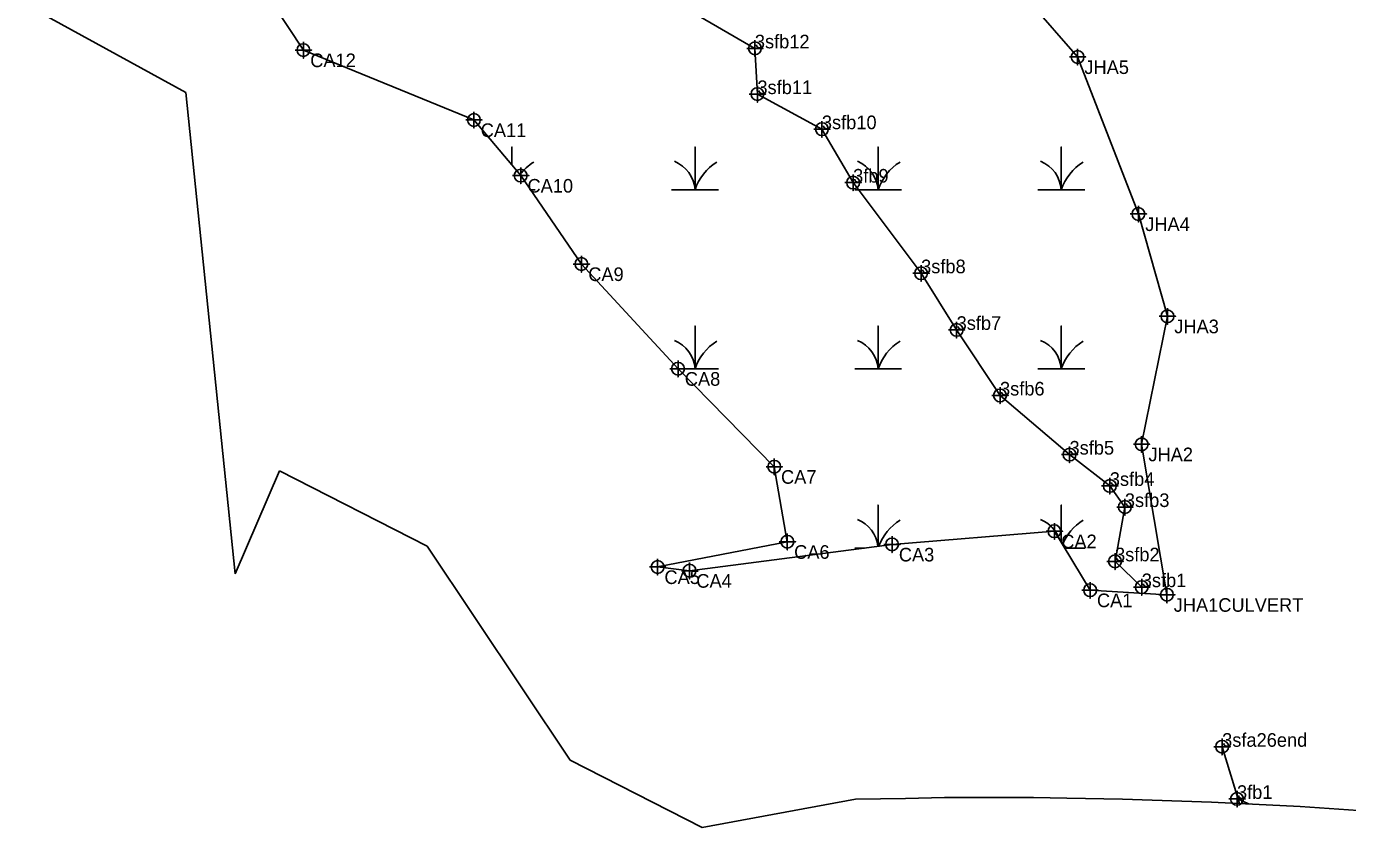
# Model space of a CAD drawing. Extents: x 2071991 to 2268989, y 436479 to 469629.
# Drawn here: x 2096416.2 to 2096901.1, y 458679.5 to 458973.7 of the extents above; entities that cross this region are included whole.
import ezdxf

# ---------------------------------------------------------------- set-up
doc = ezdxf.new("R2010")
doc.units = 0
for name, color, linetype in [('approx_PSA', 7, 'Continuous'), ('Exist Environmental Wetland Boundary', 7, 'Continuous'), ('Exist Environmental Wetland Boundary Cogo Comment', 7, 'Continuous'), ('Exist Environmental Wetland Boundary Cogo Point CELL', 7, 'Continuous'), ('Exist Hydro Jurisdictional Stream or Body of Water NEU Mitigable', 7, 'Continuous'), ('Exist Hydro Jurisdictional Stream or Body of Water NEU Mitigable Cogo Comment', 7, 'Continuous'), ('Exist Hydro Jurisdictional Stream or Body of Water NEU Mitigable Cogo Point CELL', 7, 'Continuous'), ('Exist Hydro Swamp or Marsh', 7, 'Continuous')]:
    doc.layers.add(name, color=color, linetype=linetype)

msp = doc.modelspace()

# ---------------------------------------------------------------- linework, layer by layer
at = {"layer": 'approx_PSA'}
for p, q in [((2096474.73, 458949.44), (2096416.23, 458981.59)), ((2096492.79, 458772.75), (2096474.73, 458949.44)), ((2096509.16, 458810.5), (2096492.79, 458772.75)), ((2096563.25, 458782.91), (2096509.16, 458810.5)), ((2096615.76, 458704.23), (2096563.25, 458782.91)), ((2096664.25, 458679.49), (2096615.76, 458704.23)), ((2096720.5, 458689.9), (2096664.25, 458679.49)), ((2096738.84, 458690.23), (2096720.5, 458689.9)), ((2096753.15, 458690.5), (2096738.84, 458690.23)), ((2096785.81, 458690.52), (2096753.15, 458690.5)), ((2096798.01, 458690.32), (2096785.81, 458690.52)), ((2096798.03, 458690.32), (2096798.01, 458690.32)), ((2096818.46, 458689.98), (2096798.03, 458690.32)), ((2096851.1, 458688.87), (2096818.46, 458689.98)), ((2096883.72, 458687.18), (2096851.1, 458688.87)), ((2096916.3, 458684.93), (2096883.72, 458687.18))]:
    msp.add_line(p, q, dxfattribs=at)
at = {"layer": 'Exist Environmental Wetland Boundary'}
for points in [[(2096478.67, 459024.53), (2096517.89, 458965.03), (2096580.45, 458939.37), (2096597.62, 458918.95), (2096619.91, 458886.48), (2096655.35, 458848.02), (2096690.66, 458812.02), (2096695.47, 458784.46), (2096647.88, 458775.2), (2096659.58, 458773.84), (2096733.9, 458783.48), (2096793.49, 458788.35), (2096806.6, 458766.69), (2096834.77, 458765), (2096825.49, 458820.29), (2096834.97, 458867.3), (2096824.32, 458904.85), (2096801.99, 458962.51), (2096784.25, 458982.86)], [(2096860.83, 458690.07), (2096864.73, 458688.16)]]:
    msp.add_lwpolyline(points, dxfattribs=at)
at = {"layer": 'Exist Environmental Wetland Boundary Cogo Point CELL'}
for points in [[(2096517.89, 458968.03), (2096517.89, 458962.03), (2096517.89, 458965.03), (2096520.89, 458965.03), (2096514.89, 458965.03)], [(2096801.99, 458965.51), (2096801.99, 458959.51), (2096801.99, 458962.51), (2096804.99, 458962.51), (2096798.99, 458962.51)], [(2096580.45, 458942.37), (2096580.45, 458936.37), (2096580.45, 458939.37), (2096583.45, 458939.37), (2096577.45, 458939.37)], [(2096597.62, 458921.95), (2096597.62, 458915.95), (2096597.62, 458918.95), (2096600.62, 458918.95), (2096594.62, 458918.95)], [(2096824.32, 458907.85), (2096824.32, 458901.85), (2096824.32, 458904.85), (2096827.32, 458904.85), (2096821.32, 458904.85)], [(2096619.91, 458889.48), (2096619.91, 458883.48), (2096619.91, 458886.48), (2096622.91, 458886.48), (2096616.91, 458886.48)], [(2096834.97, 458870.3), (2096834.97, 458864.3), (2096834.97, 458867.3), (2096837.97, 458867.3), (2096831.97, 458867.3)], [(2096655.35, 458851.02), (2096655.35, 458845.02), (2096655.35, 458848.02), (2096658.35, 458848.02), (2096652.35, 458848.02)], [(2096825.49, 458823.29), (2096825.49, 458817.29), (2096825.49, 458820.29), (2096828.49, 458820.29), (2096822.49, 458820.29)], [(2096690.66, 458815.02), (2096690.66, 458809.02), (2096690.66, 458812.02), (2096693.66, 458812.02), (2096687.66, 458812.02)], [(2096793.49, 458791.35), (2096793.49, 458785.35), (2096793.49, 458788.35), (2096796.49, 458788.35), (2096790.49, 458788.35)], [(2096695.47, 458787.46), (2096695.47, 458781.46), (2096695.47, 458784.46), (2096698.47, 458784.46), (2096692.47, 458784.46)], [(2096733.9, 458786.48), (2096733.9, 458780.48), (2096733.9, 458783.48), (2096736.9, 458783.48), (2096730.9, 458783.48)], [(2096647.88, 458778.2), (2096647.88, 458772.2), (2096647.88, 458775.2), (2096650.88, 458775.2), (2096644.88, 458775.2)], [(2096659.58, 458776.84), (2096659.58, 458770.84), (2096659.58, 458773.84), (2096662.58, 458773.84), (2096656.58, 458773.84)], [(2096806.6, 458769.69), (2096806.6, 458763.69), (2096806.6, 458766.69), (2096809.6, 458766.69), (2096803.6, 458766.69)], [(2096834.77, 458768), (2096834.77, 458762), (2096834.77, 458765), (2096837.77, 458765), (2096831.77, 458765)], [(2096860.49, 458693.02), (2096860.49, 458687.02), (2096860.49, 458690.02), (2096863.49, 458690.02), (2096857.49, 458690.02)]]:
    msp.add_lwpolyline(points, dxfattribs=at)
for centre in [(2096517.89, 458965.03), (2096801.99, 458962.51), (2096580.45, 458939.37), (2096597.62, 458918.95), (2096824.32, 458904.85), (2096619.91, 458886.48), (2096834.97, 458867.3), (2096655.35, 458848.02), (2096825.49, 458820.29), (2096690.66, 458812.02), (2096695.47, 458784.46), (2096793.49, 458788.35), (2096733.9, 458783.48), (2096647.88, 458775.2), (2096659.58, 458773.84), (2096806.6, 458766.69), (2096834.77, 458765), (2096860.49, 458690.02)]:
    msp.add_circle(centre, 2.34, dxfattribs=at)
at = {"layer": 'Exist Hydro Jurisdictional Stream or Body of Water NEU Mitigable'}
for points in [[(2096437.83, 459257.03), (2096456.19, 459240.49), (2096480.46, 459204.95), (2096502.68, 459180.01), (2096532.04, 459137.34), (2096548.57, 459119.82), (2096564.69, 459110.17), (2096580.46, 459082.27), (2096602.73, 459051.57), (2096614.09, 459035.56), (2096631.32, 459020.05), (2096657.61, 458980.69), (2096683.56, 458965.68), (2096684.49, 458948.88), (2096708.15, 458936), (2096719.62, 458916.38), (2096744.57, 458883.08), (2096757.6, 458862.28), (2096773.52, 458838.19), (2096799.03, 458816.48), (2096813.82, 458804.99), (2096819.34, 458797.23), (2096815.73, 458777.28), (2096825.54, 458767.8)], [(2096855.04, 458709.17), (2096861.36, 458688.34)]]:
    msp.add_lwpolyline(points, dxfattribs=at)
at = {"layer": 'Exist Hydro Jurisdictional Stream or Body of Water NEU Mitigable Cogo Point CELL'}
for points in [[(2096683.56, 458968.68), (2096683.56, 458962.68), (2096683.56, 458965.68), (2096686.56, 458965.68), (2096680.56, 458965.68)], [(2096684.49, 458951.88), (2096684.49, 458945.88), (2096684.49, 458948.88), (2096687.49, 458948.88), (2096681.49, 458948.88)], [(2096708.15, 458939), (2096708.15, 458933), (2096708.15, 458936), (2096711.15, 458936), (2096705.15, 458936)], [(2096719.62, 458919.38), (2096719.62, 458913.38), (2096719.62, 458916.38), (2096722.62, 458916.38), (2096716.62, 458916.38)], [(2096744.57, 458886.08), (2096744.57, 458880.08), (2096744.57, 458883.08), (2096747.57, 458883.08), (2096741.57, 458883.08)], [(2096757.6, 458865.28), (2096757.6, 458859.28), (2096757.6, 458862.28), (2096760.6, 458862.28), (2096754.6, 458862.28)], [(2096773.52, 458841.19), (2096773.52, 458835.19), (2096773.52, 458838.19), (2096776.52, 458838.19), (2096770.52, 458838.19)], [(2096799.03, 458819.48), (2096799.03, 458813.48), (2096799.03, 458816.48), (2096802.03, 458816.48), (2096796.03, 458816.48)], [(2096813.82, 458807.99), (2096813.82, 458801.99), (2096813.82, 458804.99), (2096816.82, 458804.99), (2096810.82, 458804.99)], [(2096819.34, 458800.23), (2096819.34, 458794.23), (2096819.34, 458797.23), (2096822.34, 458797.23), (2096816.34, 458797.23)], [(2096815.73, 458780.28), (2096815.73, 458774.28), (2096815.73, 458777.28), (2096818.73, 458777.28), (2096812.73, 458777.28)], [(2096825.54, 458770.8), (2096825.54, 458764.8), (2096825.54, 458767.8), (2096828.54, 458767.8), (2096822.54, 458767.8)], [(2096855.04, 458712.17), (2096855.04, 458706.17), (2096855.04, 458709.17), (2096858.04, 458709.17), (2096852.04, 458709.17)]]:
    msp.add_lwpolyline(points, dxfattribs=at)
for centre in [(2096683.56, 458965.68), (2096684.49, 458948.88), (2096708.15, 458936), (2096719.62, 458916.38), (2096744.57, 458883.08), (2096757.6, 458862.28), (2096773.52, 458838.19), (2096799.03, 458816.48), (2096813.82, 458804.99), (2096819.34, 458797.23), (2096815.73, 458777.28), (2096825.54, 458767.8), (2096855.04, 458709.17)]:
    msp.add_circle(centre, 2.34, dxfattribs=at)
at = {"layer": 'Exist Hydro Swamp or Marsh'}
for p, q in [((2096601.21, 458913.73), (2096602.99, 458913.73)), ((2096720.19, 458782.16), (2096723.75, 458782.16)), ((2096797.24, 458782.16), (2096804.6, 458782.16)), ((2096862.01, 458689.03), (2096862.97, 458689.03))]:
    msp.add_line(p, q, dxfattribs=at)
for points in [[(2096594.39, 458922.8), (2096594.39, 458929.51), (2096594.39, 458922.8)], [(2096652.99, 458913.73), (2096661.59, 458913.73), (2096661.59, 458929.51), (2096661.59, 458913.73), (2096670.19, 458913.73)], [(2096720.19, 458913.73), (2096728.79, 458913.73), (2096728.79, 458929.51), (2096728.79, 458913.73), (2096737.4, 458913.73)], [(2096787.4, 458913.73), (2096796, 458913.73), (2096796, 458929.51), (2096796, 458913.73), (2096804.6, 458913.73)], [(2096655.43, 458847.94), (2096661.59, 458847.94), (2096661.59, 458863.73), (2096661.59, 458847.94), (2096670.19, 458847.94)], [(2096720.19, 458847.94), (2096728.79, 458847.94), (2096728.79, 458863.73), (2096728.79, 458847.94), (2096737.4, 458847.94)], [(2096787.4, 458847.94), (2096796, 458847.94), (2096796, 458863.73), (2096796, 458847.94), (2096804.6, 458847.94)], [(2096728.79, 458782.82), (2096728.79, 458797.94), (2096728.79, 458782.82)], [(2096796, 458784.22), (2096796, 458797.94), (2096796, 458784.22)]]:
    msp.add_lwpolyline(points, dxfattribs=at)
for centre, radius, start, end in [((2096612.63, 458907.66), 19.22, 122.1274, 142.7465), ((2096649.32, 458912.84), 12.3, 4.1403, 67.535), ((2096679.83, 458907.66), 19.22, 122.1274, 161.6222), ((2096716.53, 458912.84), 12.3, 4.1403, 67.535), ((2096747.04, 458907.66), 19.22, 122.1274, 161.6222), ((2096783.73, 458912.84), 12.3, 4.1403, 67.535), ((2096814.24, 458907.66), 19.22, 122.1274, 161.6222), ((2096649.32, 458847.06), 12.3, 4.1403, 67.535), ((2096679.83, 458841.88), 19.22, 122.1274, 161.6222), ((2096716.53, 458847.06), 12.3, 4.1403, 67.535), ((2096747.04, 458841.88), 19.22, 122.1274, 161.6222), ((2096783.73, 458847.06), 12.3, 4.1403, 67.535), ((2096814.24, 458841.88), 19.22, 122.1274, 161.6222), ((2096716.53, 458781.28), 12.3, 7.1678, 67.535), ((2096747.04, 458776.1), 19.22, 122.1274, 159.4522), ((2096783.73, 458781.28), 12.3, 18.8875, 67.535), ((2096814.24, 458776.1), 19.22, 122.1274, 157.579)]:
    msp.add_arc(centre, radius, start, end, dxfattribs=at)

# ---------------------------------------------------------------- texts
at = {"layer": 'Exist Environmental Wetland Boundary Cogo Comment'}
for s, p in [('CA12', (2096520.39, 458958.78)), ('JHA5', (2096804.49, 458956.26)), ('CA11', (2096582.95, 458933.12)), ('CA10', (2096600.12, 458912.7)), ('JHA4', (2096826.82, 458898.6)), ('CA9', (2096622.41, 458880.23)), ('JHA3', (2096837.47, 458861.05)), ('CA8', (2096657.85, 458841.77)), ('JHA2', (2096827.99, 458814.04)), ('CA7', (2096693.16, 458805.77)), ('CA2', (2096795.99, 458782.1)), ('CA6', (2096697.97, 458778.21)), ('CA3', (2096736.4, 458777.23)), ('CA5', (2096650.38, 458768.95)), ('CA4', (2096662.08, 458767.59)), ('CA1', (2096809.1, 458760.44)), ('JHA1CULVERT', (2096837.27, 458758.75)), ('3fb1', (2096860.49, 458690.02))]:
    msp.add_text(s, height=5, dxfattribs=at).set_placement(p)
at = {"layer": 'Exist Hydro Jurisdictional Stream or Body of Water NEU Mitigable Cogo Comment'}
for s, p in [('3sfb12', (2096683.56, 458965.68)), ('3sfb11', (2096684.49, 458948.88)), ('3sfb10', (2096708.15, 458936)), ('3fb9', (2096719.62, 458916.38)), ('3sfb8', (2096744.57, 458883.08)), ('3sfb7', (2096757.6, 458862.28)), ('3sfb6', (2096773.52, 458838.19)), ('3sfb5', (2096799.03, 458816.48)), ('3sfb4', (2096813.82, 458804.99)), ('3sfb3', (2096819.34, 458797.23)), ('3sfb2', (2096815.73, 458777.28)), ('3sfb1', (2096825.54, 458767.8)), ('3sfa26end', (2096855.04, 458709.17))]:
    msp.add_text(s, height=5, dxfattribs=at).set_placement(p)

doc.saveas('drawing.dxf')
